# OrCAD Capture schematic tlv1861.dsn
size A
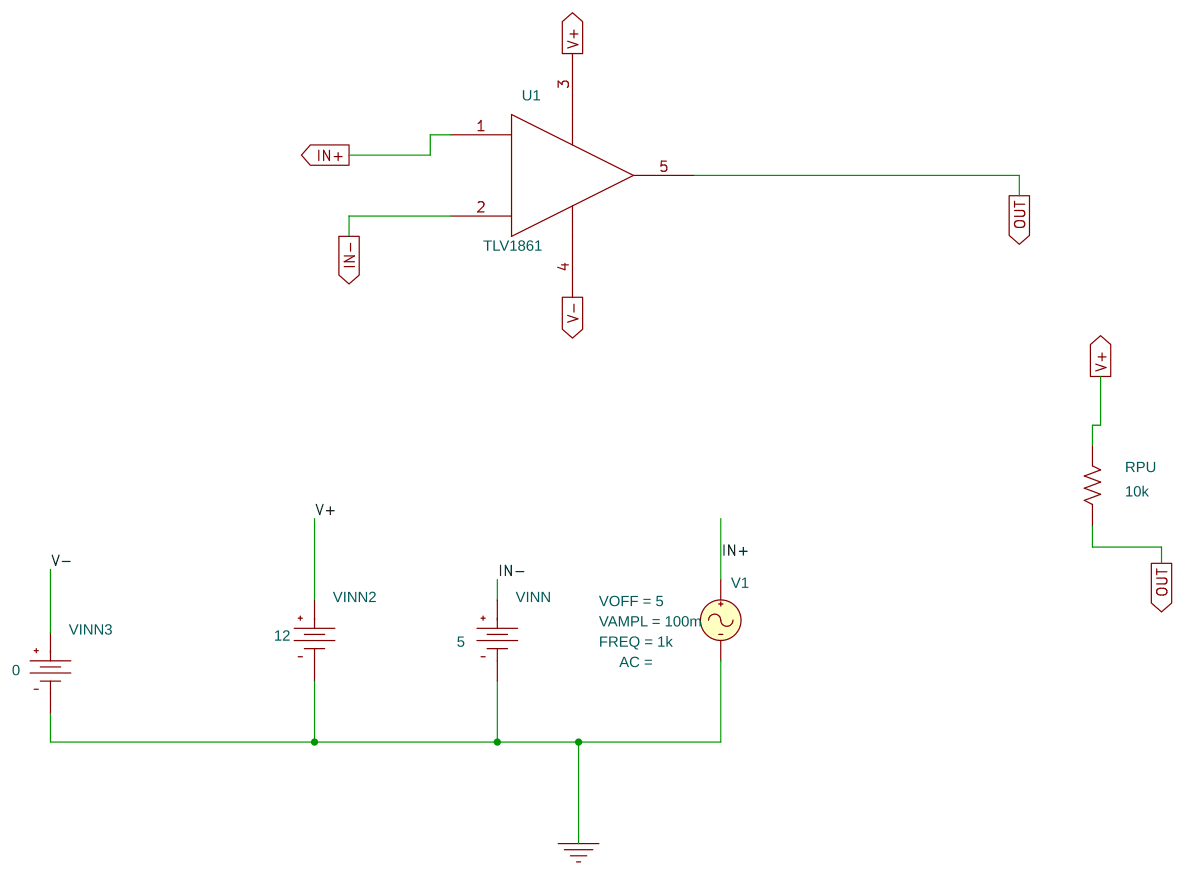
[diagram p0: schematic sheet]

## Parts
RPU  10k  [AXRC05]
U1  TLV1861
V1  VSIN
VINN  VDC
VINN2  VDC
VINN3  VDC

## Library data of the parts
RPU = R
U1 = TLV1861
V1 = VSIN: FREQ: 1k; VAMPL: 100m; VOFF: 5
VINN = VDC: DC: 5
VINN2 = VDC: DC: 12
VINN3 = VDC: DC: 0

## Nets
0: V1.2(-) VINN.1(-) VINN2.1(-) VINN3.1(-)
IN+: U1.1(IN+) V1.1(+)
IN-: U1.2(IN-) VINN.0(+)
OUT: RPU.1 U1.5(OUT)
V+: RPU.2 U1.3(V+) VINN2.0(+)
V-: U1.4(V-) VINN3.0(+)
